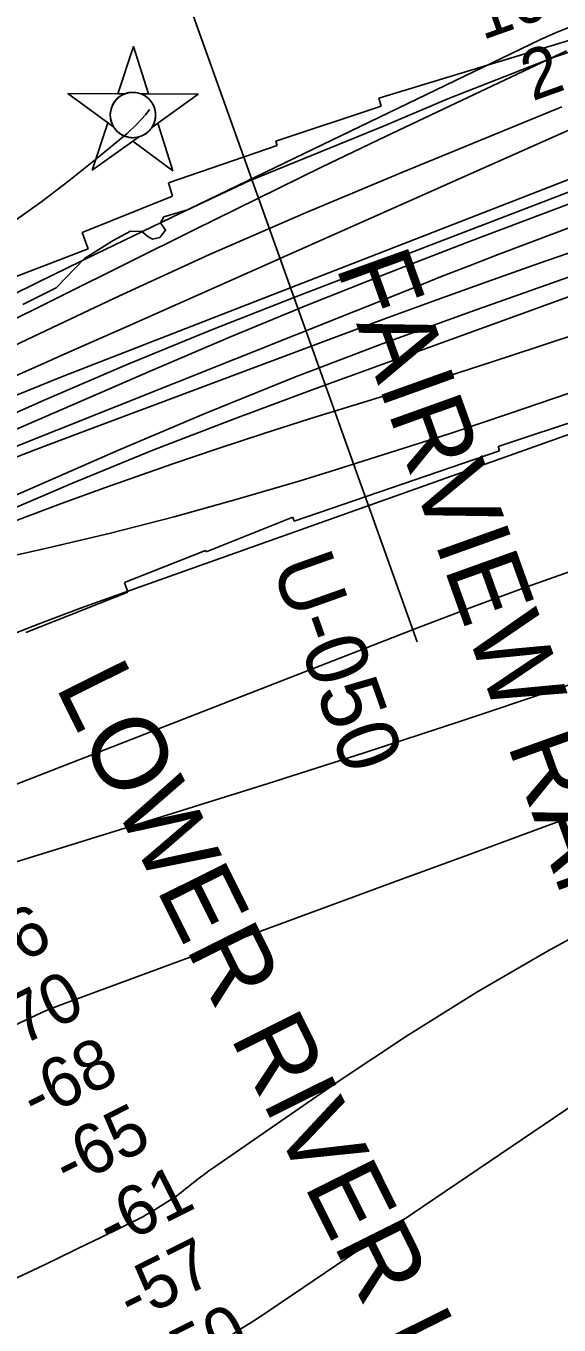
# Model space of a CAD drawing. Extents: x 3598634 to 3636690, y 517270 to 542944.
# Drawn here: x 3613688 to 3614405, y 535354 to 537102 of the extents above; entities that cross this region are included whole.
import ezdxf

# ---------------------------------------------------------------- set-up
doc = ezdxf.new("R2010")
doc.units = 0
for name, color, linetype in [('V-CHAN-NAID', 7, 'Continuous'), ('V-RIVR-EDGE', 7, 'Continuous'), ('V-RIVR-RANG', 7, 'Continuous'), ('V-RIVR-RANG-IDEN', 7, 'Continuous'), ('V-RRAP-RVMT', 7, 'Continuous'), ('V-TOPO-DPTH', 7, 'Continuous'), ('V-TOPO-MAJR', 7, 'Continuous'), ('V-TOPO-MINR', 7, 'Continuous'), ('V-TOPO-WATR', 7, 'Continuous')]:
    doc.layers.add(name, color=color, linetype=linetype)

msp = doc.modelspace()

# ---------------------------------------------------------------- linework, layer by layer
at = {"layer": 'V-CHAN-NAID'}
for points in [[(3613821.4, 537010.8), (3613811.8, 537010.8), (3613832.9, 537074.3), (3613853.1, 537010.5), (3613843.6, 537010.6), (3613842, 537011.2), (3613839.9, 537011.8), (3613837.8, 537012.2), (3613835.8, 537012.6), (3613834.6, 537012.7), (3613833.1, 537012.7), (3613831.4, 537012.7), (3613830, 537012.7), (3613828.1, 537012.5), (3613826.7, 537012.3), (3613825, 537011.9), (3613823.4, 537011.4), (3613822.4, 537011.1)], [(3613821.4, 537010.8), (3613744.9, 537011.3), (3613806.5, 536965.9), (3613805.3, 536967.8), (3613804.5, 536969.4), (3613803.7, 536971.4), (3613803, 536973.5), (3613802.6, 536974.8), (3613802.3, 536976.4), (3613802, 536977.8), (3613801.9, 536979.4), (3613801.7, 536981.2), (3613801.7, 536982.8), (3613801.8, 536984.8), (3613802, 536986.5), (3613802.4, 536988.7), (3613802.9, 536990.6), (3613803.5, 536992.5), (3613804.2, 536994.1), (3613804.9, 536995.7), (3613805.7, 536997.3), (3613806.8, 536999), (3613807.8, 537000.5), (3613808.8, 537001.7), (3613809.8, 537002.9), (3613811.1, 537004.2), (3613812.1, 537005.2), (3613813.9, 537006.6), (3613815.1, 537007.5), (3613816.8, 537008.5), (3613818.5, 537009.5), (3613819.9, 537010.2)], [(3613843.6, 537010.6), (3613920, 537010.1), (3613857.8, 536965.5), (3613858.8, 536967), (3613859.7, 536968.9), (3613860.4, 536970.4), (3613861.2, 536972.4), (3613861.7, 536974.2), (3613862.1, 536975.8), (3613862.5, 536977.8), (3613862.7, 536979.4), (3613862.8, 536981.6), (3613862.8, 536983.7), (3613862.6, 536985.9), (3613862.3, 536987.7), (3613861.8, 536989.9), (3613861.2, 536992), (3613860.4, 536994), (3613859.8, 536995.5), (3613858.8, 536997.4), (3613857.7, 536999.1), (3613856.5, 537000.8), (3613855.2, 537002.3), (3613854, 537003.7), (3613852.3, 537005.2), (3613850.6, 537006.6), (3613848.9, 537007.8), (3613847, 537009), (3613845.6, 537009.7)], [(3613839.8, 536952.6), (3613777.6, 536908.1), (3613798.7, 536971.6), (3613806.5, 536965.9), (3613807.1, 536964.9), (3613808.5, 536963.1), (3613809.7, 536961.7), (3613811.1, 536960.2), (3613812.5, 536958.9), (3613814, 536957.7), (3613815.4, 536956.8), (3613817.1, 536955.7), (3613818.8, 536954.8), (3613820.6, 536954), (3613822, 536953.4), (3613823.7, 536952.9), (3613825.9, 536952.4), (3613827.4, 536952.1), (3613829.4, 536951.8), (3613831, 536951.7), (3613832.8, 536951.7), (3613834.5, 536951.8), (3613836.2, 536951.9), (3613838.1, 536952.2)], [(3613857.8, 536965.5), (3613865.6, 536971.1), (3613885.9, 536907.3), (3613832, 536947), (3613839.8, 536952.6), (3613841.5, 536953.1), (3613843.1, 536953.7), (3613845.2, 536954.6), (3613847, 536955.5), (3613848.9, 536956.6), (3613850.6, 536957.8), (3613852.1, 536959), (3613853.4, 536960.2), (3613854.8, 536961.6), (3613856, 536963), (3613857.1, 536964.5)]]:
    msp.add_lwpolyline(points, close=True, dxfattribs=at)
msp.add_circle((3613832.3, 536982.2), 30.5, dxfattribs=at)
at = {"layer": 'V-RIVR-EDGE'}
msp.add_lwpolyline([(3614552.8, 537112.3), (3614398.9, 537060), (3614256, 537004), (3614169.5, 536967.4), (3613987.9, 536893.1), (3613905.7, 536854.7), (3613873.8, 536845), (3613869.5, 536837.1), (3613876.3, 536827.2), (3613868.3, 536817.5), (3613858.5, 536815), (3613852.3, 536818.7), (3613844.4, 536825.5), (3613829.1, 536826.1), (3613805.8, 536813.3), (3613767.1, 536788.9), (3613729, 536749.8), (3613684.2, 536727.2)], dxfattribs=at)
at = {"layer": 'V-RIVR-RANG'}
msp.add_line((3613850.9, 537290.3), (3614214.6, 536273.3), dxfattribs=at)
at = {"layer": 'V-RRAP-RVMT'}
for p, q in [((3614456.9, 537094), (3614163, 537005.1)), ((3614166.2, 536993.9), (3614024.6, 536947.2)), ((3614163, 537005.1), (3614166.2, 536993.9)), ((3614026.1, 536941.1), (3613880, 536890.8)), ((3614024.6, 536947.2), (3614026.1, 536941.1)), ((3613880, 536890.8), (3613885.7, 536873)), ((3613885.7, 536873), (3613764, 536823.9)), ((3613764, 536823.9), (3613772, 536802)), ((3613772, 536802), (3613651.6, 536756.1)), ((3614323.8, 536536.2), (3614447.4, 536577.3)), ((3614325.5, 536530.5), (3614323.8, 536536.2)), ((3614049.1, 536435.7), (3614325.5, 536530.5)), ((3613930.6, 536394.2), (3614047.2, 536441)), ((3614047.2, 536441), (3614049.1, 536435.7)), ((3613820.9, 536353), (3613929.7, 536396.3)), ((3613929.7, 536396.3), (3613930.6, 536394.2)), ((3613825.4, 536339.9), (3613820.9, 536353)), ((3613688.4, 536285.9), (3613825.4, 536339.9))]:
    msp.add_line(p, q, dxfattribs=at)
at = {"layer": 'V-TOPO-DPTH'}
for points in [[(3614421.8, 537101.2), (3614400.6, 537092.6), (3614379.7, 537083.2), (3613781.9, 536794.8), (3613704.8, 536757.3), (3613627.9, 536719.5), (3613551.2, 536681.3), (3613474.6, 536642.8), (3613389, 536599.4), (3613355.4, 536582.3), (3613321.8, 536565.3), (3613288.1, 536548.2), (3613254.5, 536531.1), (3613172.9, 536489.7), (3613098.5, 536451.7), (3613024.3, 536413.6), (3612950.2, 536375.2), (3612876.2, 536336.5), (3612348.3, 536059.5)], [(3614409.4, 536993.1), (3614193.8, 536904.9), (3614064.2, 536850.4), (3613935.4, 536794.3), (3613807.7, 536735.7), (3613680.7, 536675.5), (3613363.4, 536521.2), (3613355.5, 536517.4), (3613347.5, 536513.5), (3613339.6, 536509.6), (3613331.7, 536505.7), (3612558.5, 536124.2), (3612518.6, 536104.4)], [(3612518.6, 536104.4), (3612558.5, 536124.2), (3613331.7, 536505.7), (3613339.6, 536509.6), (3613347.5, 536513.5), (3613355.5, 536517.4), (3613363.4, 536521.2), (3613680.7, 536675.5), (3613807.7, 536735.7), (3613935.4, 536794.3), (3614064.2, 536850.4), (3614193.8, 536904.9), (3614409.4, 536993.1)], [(3614435.5, 536902.1), (3613737.7, 536630.2), (3613675.5, 536605.3), (3613613.7, 536579.7), (3613552.3, 536552.9), (3613491.3, 536525.3), (3613431.3, 536497.6), (3613400.6, 536483.2), (3613369.8, 536468.7), (3613339.2, 536453.9), (3613308.7, 536439), (3613201, 536385.8), (3613116.8, 536343.8), (3613032.9, 536301.4), (3612949.4, 536258.1), (3612866.1, 536214.4), (3612390.4, 535961.9)], [(3612390.4, 535961.9), (3612866.1, 536214.4), (3612949.4, 536258.1), (3613032.9, 536301.4), (3613116.8, 536343.8), (3613201, 536385.8), (3613308.7, 536439), (3613339.2, 536453.9), (3613369.8, 536468.7), (3613400.6, 536483.2), (3613431.3, 536497.6), (3613491.3, 536525.3), (3613552.3, 536552.9), (3613613.7, 536579.7), (3613675.5, 536605.3), (3613737.7, 536630.2), (3614435.5, 536902.1)], [(3612433.9, 535935), (3613361.1, 536420.8), (3613374.1, 536427.4), (3613387.2, 536433.9), (3613400.4, 536440), (3613413.7, 536446), (3613858.7, 536638.9), (3613963.7, 536683.6), (3614069.1, 536727.2), (3614175.2, 536769.4), (3614281.6, 536810.5), (3614475.1, 536883.7)], [(3614475.1, 536883.7), (3614281.6, 536810.5), (3614175.2, 536769.4), (3614069.1, 536727.2), (3613963.7, 536683.6), (3613858.7, 536638.9), (3613413.7, 536446), (3613400.4, 536440), (3613387.2, 536433.9), (3613374.1, 536427.4), (3613361.1, 536420.8), (3612433.9, 535935)], [(3612442.8, 535897.5), (3612636.8, 536010.9), (3612759.7, 536081.6), (3612883.1, 536151.2), (3613007.4, 536219.2), (3613132.3, 536286.2), (3613377.5, 536415.5), (3613385, 536419.3), (3613392.6, 536423), (3613400.3, 536426.4), (3613408.1, 536429.6), (3614210.9, 536750.3), (3614248.4, 536765.2), (3614286, 536779.9), (3614323.7, 536794.4), (3614361.5, 536808.7), (3614403.2, 536824.4), (3614420.2, 536830.7)], [(3614420.2, 536830.7), (3614403.2, 536824.4), (3614361.5, 536808.7), (3614323.7, 536794.4), (3614286, 536779.9), (3614248.4, 536765.2), (3614210.9, 536750.3), (3613408.1, 536429.6), (3613400.3, 536426.4), (3613392.6, 536423), (3613385, 536419.3), (3613377.5, 536415.5), (3613132.3, 536286.2), (3613007.4, 536219.2), (3612883.1, 536151.2), (3612759.7, 536081.6), (3612636.8, 536010.9), (3612442.8, 535897.5)], [(3612478.9, 535874.5), (3613205.1, 536306.1), (3613236.8, 536324.6), (3613268.6, 536342.8), (3613300.7, 536360.5), (3613333, 536378), (3613393.8, 536410.2), (3613395.9, 536411.2), (3613398, 536412.3), (3613402.2, 536414.1), (3613518.3, 536460.4), (3613578.6, 536484.3), (3613638.9, 536507.9), (3613699.4, 536531.1), (3613760, 536554), (3614103.4, 536683), (3614172.1, 536708.5), (3614240.9, 536733.7), (3614309.9, 536758.3), (3614379, 536782.7), (3614463.6, 536812.1)], [(3614463.6, 536812.1), (3614379, 536782.7), (3614309.9, 536758.3), (3614240.9, 536733.7), (3614172.1, 536708.5), (3614103.4, 536683), (3613760, 536554), (3613699.4, 536531.1), (3613638.9, 536507.9), (3613578.6, 536484.3), (3613518.3, 536460.4), (3613402.2, 536414.1), (3613398, 536412.3), (3613395.9, 536411.2), (3613393.8, 536410.2), (3613333, 536378), (3613300.7, 536360.5), (3613268.6, 536342.8), (3613236.8, 536324.6), (3613205.1, 536306.1), (3612478.9, 535874.5)]]:
    msp.add_lwpolyline(points, dxfattribs=at)
at = {"layer": 'V-TOPO-MAJR'}
for points in [[(3614502.9, 536793.9), (3614287.6, 536718), (3614167.7, 536674.3), (3614048.5, 536628.9), (3613930.3, 536580.8), (3613812.9, 536531), (3613466.7, 536379.7), (3613445.3, 536370), (3613424, 536359.9), (3613403.1, 536349.2), (3613382.3, 536338.1), (3612621.7, 535919.1), (3612588.7, 535900.6), (3612555.8, 535882), (3612523.1, 535863)], [(3612505.3, 534181.1), (3613019.1, 534660.7), (3613020.6, 534662.5), (3613022.9, 534664.7), (3613023.5, 534665.2), (3613027.7, 534668.3), (3613028.3, 534668.8), (3613030.1, 534670), (3613299.7, 534863.2), (3613406.6, 534939.8), (3613513.4, 535016.4), (3613620.1, 535093.2), (3613726.8, 535170.1), (3613915.8, 535306.4), (3613928, 535315.1), (3613940.2, 535323.6), (3613952.5, 535332.1), (3613964.8, 535340.4), (3613977.3, 535348.6), (3613989.9, 535356.6), (3614002.5, 535364.5), (3614826.9, 535922.5)]]:
    msp.add_lwpolyline(points, dxfattribs=at)
at = {"layer": 'V-TOPO-MINR'}
for points in [[(3614421.8, 537101.2), (3614400.6, 537092.6), (3614379.7, 537083.2), (3613781.9, 536794.8), (3613704.8, 536757.3), (3613627.9, 536719.5), (3613551.2, 536681.3), (3613474.6, 536642.8), (3613389, 536599.4), (3613355.4, 536582.3), (3613321.8, 536565.3), (3613288.1, 536548.2), (3613254.5, 536531.1), (3613172.9, 536489.7), (3613098.5, 536451.7), (3613024.3, 536413.6), (3612950.2, 536375.2), (3612876.2, 536336.5), (3612348.3, 536059.5)], [(3614415.6, 537068.6), (3614258.3, 536994.3), (3614172.1, 536953.2), (3614086.1, 536911.8), (3614000.3, 536869.9), (3613914.7, 536827.7), (3613376.3, 536560.1), (3613355.5, 536549.7), (3613334.7, 536539.4), (3613313.8, 536529), (3613293, 536518.6), (3612947, 536345.5), (3612840.7, 536292.1), (3612734.5, 536238.2), (3612628.5, 536184), (3612522.8, 536129.3)], [(3613854.4, 536989.6), (3613849.7, 536982.9), (3613837.6, 536969.7), (3613824.4, 536957.3), (3613781.9, 536922.2), (3613746.1, 536893.6), (3613709.8, 536865.8), (3613672.4, 536839.3), (3613634.5, 536813.7), (3613377.7, 536646.4), (3613341.1, 536623.1), (3613304.2, 536600.2), (3613266.9, 536578.1), (3613229.2, 536556.5), (3613201.8, 536541.1), (3613150.1, 536512.3), (3613098.4, 536483.6), (3613046.4, 536455.3), (3612994.4, 536427.2), (3612323.9, 536067.2)], [(3614448.9, 536975.1), (3613824.3, 536697.8), (3613758, 536668.4), (3613691.8, 536638.9), (3613625.5, 536609.5), (3613559.3, 536580), (3613460.7, 536536.1), (3613443.8, 536528.5), (3613426.8, 536520.9), (3613410, 536513.1), (3613393.1, 536505.3), (3613376.3, 536497.5), (3613359.5, 536489.5), (3613342.7, 536481.5), (3613326, 536473.5), (3613315.2, 536468.3), (3613293.2, 536457.4), (3613271.2, 536446.5), (3613249.3, 536435.4), (3613227.5, 536424.1), (3612400.2, 535992.7)], [(3614455.3, 536892.9), (3614050.2, 536737.3), (3613937, 536692.6), (3613824.4, 536646.6), (3613712.7, 536598.6), (3613601.5, 536549.2), (3613420.8, 536467), (3613400.4, 536457.6), (3613380.1, 536448), (3613360, 536438.2), (3613339.9, 536428.2), (3612922.5, 536217.6), (3612828.6, 536169.7), (3612735, 536121.2), (3612641.8, 536071.9), (3612548.9, 536022.1), (3612380.7, 535930.8)], [(3614435.5, 536902.1), (3613737.7, 536630.2), (3613675.5, 536605.3), (3613613.7, 536579.7), (3613552.3, 536552.9), (3613491.3, 536525.3), (3613431.3, 536497.6), (3613400.6, 536483.2), (3613369.8, 536468.7), (3613339.2, 536453.9), (3613308.7, 536439), (3613201, 536385.8), (3613116.8, 536343.8), (3613032.9, 536301.4), (3612949.4, 536258.1), (3612866.1, 536214.4), (3612390.4, 535961.9)], [(3614475.1, 536883.7), (3614281.6, 536810.5), (3614175.2, 536769.4), (3614069.1, 536727.2), (3613963.7, 536683.6), (3613858.7, 536638.9), (3613413.7, 536446), (3613400.4, 536440), (3613387.2, 536433.9), (3613374.1, 536427.4), (3613361.1, 536420.8), (3612433.9, 535935)], [(3614420.2, 536830.7), (3614403.2, 536824.4), (3614361.5, 536808.7), (3614323.7, 536794.4), (3614286, 536779.9), (3614248.4, 536765.2), (3614210.9, 536750.3), (3613408.1, 536429.6), (3613400.3, 536426.4), (3613392.6, 536423), (3613385, 536419.3), (3613377.5, 536415.5), (3613132.3, 536286.2), (3613007.4, 536219.2), (3612883.1, 536151.2), (3612759.7, 536081.6), (3612636.8, 536010.9), (3612442.8, 535897.5)], [(3614463.6, 536812.1), (3614379, 536782.7), (3614309.9, 536758.3), (3614240.9, 536733.7), (3614172.1, 536708.5), (3614103.4, 536683), (3613760, 536554), (3613699.4, 536531.1), (3613638.9, 536507.9), (3613578.6, 536484.3), (3613518.3, 536460.4), (3613402.2, 536414.1), (3613398, 536412.3), (3613395.9, 536411.2), (3613393.8, 536410.2), (3613333, 536378), (3613300.7, 536360.5), (3613268.6, 536342.8), (3613236.8, 536324.6), (3613205.1, 536306.1), (3612478.9, 535874.5)], [(3614534.2, 536779.5), (3614076.9, 536613.9), (3613967.6, 536573.1), (3613858.9, 536531), (3613751.1, 536486.8), (3613643.8, 536441.2), (3613459.9, 536360.9), (3613445, 536354.2), (3613430.3, 536347.2), (3613415.8, 536339.8), (3613401.5, 536332.2), (3613035, 536130.1), (3612934.4, 536073.9), (3612834.2, 536017), (3612734.7, 535958.9), (3612635.6, 535900.2), (3612490.3, 535813)], [(3614506.8, 536713.3), (3614377, 536670.2), (3614315.7, 536650.1), (3614254.4, 536630.4), (3614192.8, 536611.2), (3614131.2, 536592.3), (3614069.6, 536573.3), (3614008.2, 536553.8), (3613947, 536533.4), (3613886, 536512.6), (3613795.5, 536480.9), (3613734.7, 536458.9), (3613674.3, 536436)], [(3614568.4, 536605.7), (3613815.4, 536338), (3613761.9, 536318.5), (3613708.5, 536298.6), (3613655.4, 536277.8), (3613602.5, 536256.6), (3613573.1, 536244.5), (3613535.3, 536228.4), (3613497.9, 536211.5), (3613460.9, 536193.5), (3613424.3, 536174.8), (3613358.5, 536139.9), (3613289.5, 536102.9), (3613220.6, 536065.4), (3613152.2, 536027.3), (3613084, 535988.7), (3612521.6, 535667.3)], [(3613572.2, 536366.9), (3613716.4, 536399.3), (3613802.3, 536419.7), (3613887.7, 536441.4), (3613972.6, 536465.1), (3614057.2, 536490.1), (3614097.7, 536502.6), (3614178.4, 536527.9), (3614258.8, 536553.8), (3614339, 536580.5), (3614419, 536607.8)], [(3612520.7, 535526.8), (3612526.8, 535529.2), (3612532.8, 535531.8), (3612557.6, 535542.8), (3612560.5, 535544.1), (3612563.4, 535545.5), (3612566.2, 535546.8), (3612569.1, 535548.2), (3613519.9, 536017.1), (3613529.9, 536022), (3613540, 536026.8), (3613550.2, 536031.4), (3613560.4, 536036), (3613570.6, 536040.5), (3613580.9, 536044.8), (3613591.3, 536049), (3613601.7, 536053.2), (3614216.6, 536292.7), (3614289.3, 536320.4), (3614362.3, 536347.4), (3614435.7, 536373.3)], [(3614700.3, 536310.7), (3614400.5, 536209.1), (3614272, 536166.2), (3614143.3, 536123.9), (3614014.3, 536082.7), (3613885, 536042.1), (3613627.1, 535962.3), (3613625.2, 535961.7), (3613622.9, 535960.8), (3613618.7, 535958.7), (3613614.5, 535956.6), (3613610.4, 535954.4), (3612656.3, 535447.7), (3612640.2, 535439.4), (3612624, 535431.3), (3612607.7, 535423.4), (3612591.3, 535415.8), (3612497.9, 535373.5)], [(3612491.5, 535078.8), (3612573, 535126.1), (3612713, 535207.8), (3612724.4, 535214.4), (3612735.7, 535221), (3612747.2, 535227.5), (3612758.6, 535234.1), (3613641.3, 535739.6), (3613653.3, 535746.3), (3613665.3, 535752.8), (3613677.4, 535759), (3613689.7, 535765.1), (3613702.1, 535770.9), (3613714.6, 535776.5), (3613727.2, 535781.6), (3613740, 535786.5), (3614192.7, 535953.3), (3614287.2, 535988.1), (3614381.7, 536022.8), (3614476.2, 536057.5)], [(3613665.2, 535412.3), (3613696.3, 535427), (3613727.4, 535441.8), (3613758.3, 535456.7), (3613789.2, 535471.8), (3613840.1, 535497), (3613845.4, 535499.7), (3613850.7, 535502.6), (3613855.8, 535505.5), (3613860.9, 535508.6), (3613884.2, 535523.1), (3613887.5, 535525.2), (3613890.8, 535527.5), (3613894, 535529.8), (3613897.1, 535532.2), (3613900.1, 535534.7), (3613903.2, 535537.1), (3613906.3, 535539.6), (3613909.4, 535542.1), (3613915.5, 535546.9), (3613921.8, 535551.8), (3613928, 535556.5), (3613934.4, 535561.2), (3613940.9, 535565.7), (3614109.5, 535682.3), (3614201.4, 535743.4), (3614294.7, 535802), (3614390.1, 535857.2), (3614486.9, 535910)]]:
    msp.add_lwpolyline(points, dxfattribs=at)
at = {"layer": 'V-TOPO-WATR'}
msp.add_lwpolyline([(3614409.4, 536993.1), (3614193.8, 536904.9), (3614064.2, 536850.4), (3613935.4, 536794.3), (3613807.7, 536735.7), (3613680.7, 536675.5), (3613363.4, 536521.2), (3613355.5, 536517.4), (3613347.5, 536513.5), (3613339.6, 536509.6), (3613331.7, 536505.7), (3612558.5, 536124.2), (3612518.6, 536104.4)], dxfattribs=at)

# ---------------------------------------------------------------- texts
at = {"layer": 'V-CHAN-NAID'}
for s, rotation, p in [('FAIRVIEW RANGE A FRONT (115.0)', 289.7338, (3614104.7, 536778.4)), ('LOWER RIVER LAUNCH AMA (115.0) (2)', 296.472, (3613727.2, 536213.7)), ('CRESCENT LAUNCH AMA (115.1) (2)', 297.6305, (3613169.8, 535940.6))]:
    msp.add_text(s, height=100, rotation=rotation, dxfattribs=at).set_placement(p)
at = {"layer": 'V-RIVR-RANG'}
for s, rotation, p in [('10.7', 19.6483, (3614302.2, 537082.6)), ('2.1', 19.6483, (3614369.6, 537000.5)), ('-76', 26.6172, (3613611.9, 535805.9)), ('-70', 26.6172, (3613655.8, 535716)), ('-68', 26.6172, (3613701.1, 535626.8)), ('-65', 26.6172, (3613744.7, 535536.9)), ('-61', 26.6172, (3613803.2, 535454.3)), ('-57', 26.6172, (3613831.1, 535356.4)), ('-50', 26.6172, (3613877.3, 535267.7))]:
    msp.add_text(s, height=67, rotation=rotation, dxfattribs=at).set_placement(p)
at = {"layer": 'V-RIVR-RANG-IDEN'}
msp.add_text('U-050', height=83, rotation=289.5333, dxfattribs=at).set_placement((3614018.3, 536375.8))

doc.saveas('drawing.dxf')
